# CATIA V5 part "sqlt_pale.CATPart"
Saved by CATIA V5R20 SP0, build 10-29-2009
Part number: sqlt_pale
Publications: "longueur_pale", "largeur_pale", "Plan.1", "Point.1", "Droite.1", "Plan.2", "Point.2", "Point.3", "Point.4", "Point.5", "Point.10", "Point.11", "Point.12", "Plan.3", "Plan.4", "hauteur_pale"
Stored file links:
  D:\ecole\thinkmotion\sqlt_pale.CATPart
  D:\ecole\thinkmotion\sqlt_eolienne.CATProduct
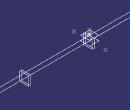
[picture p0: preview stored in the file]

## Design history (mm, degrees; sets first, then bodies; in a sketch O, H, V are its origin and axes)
Parameters
  longueur_pale = 500 mm {= External.longueur_pale}
  largeur_pale = 300 mm {= External.largeur_pale}
  hauteur_pale = 2000 mm {= External.hauteur_pale}
External parameters (linked from other documents)
  `External.diamètre_trou` = 40 mm
  `External.rayon_pivot_pale-rayon_support` = 30 mm
  External.hauteur_pivot_pale = 50 mm
  External.longueur_pale = 500 mm
  External.largeur_pale = 300 mm
  External.hauteur_pale = 2000 mm
Set1 "pale"
  Plane1: type Offset, RefPlane xy-plane, Offset 0
  Point1: (0, 0, 0)
  Line1: type PtDir, RefPoint Point1, Direction yz-plane, Start 0, End 20
  Plane2: type Offset, RefPlane yz-plane, Offset 0
  Point2: (0, 500 {= longueur_pale}, 0)
  Point3: (0, -500 {= -longueur_pale}, 0)
  Point4: (0, 0, 300 {= largeur_pale})
  Point5: type Between, FirstPoint Point4, SecondPoint Point3, Ratio 0
  Point6: type Between, FirstPoint Point5, SecondPoint Point1, Ratio 0.5
  Point7: (0, 0, 20 {= `External.diamètre_trou` /2}), relative to Point6
  Point8: (0, 0, 50 {= `External.rayon_pivot_pale-rayon_support` +`External.diamètre_trou` /2}), relative to Point6
  Plane3: type Offset, RefPlane Plane2, Offset 2000 {= hauteur_pale}
  Plane4: type Offset, RefPlane Plane2, Offset 50 {= External.hauteur_pivot_pale}
  Plane5: type Offset, RefPlane Plane4, Offset 2000 {= hauteur_pale}
  Line2: type PtDir, RefPoint Point6, Direction Plane2, Start 0, End 20
  Plane6: type OffsetPt, RefPlane Plane1, RefPoint Point6
Body1 (main body)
